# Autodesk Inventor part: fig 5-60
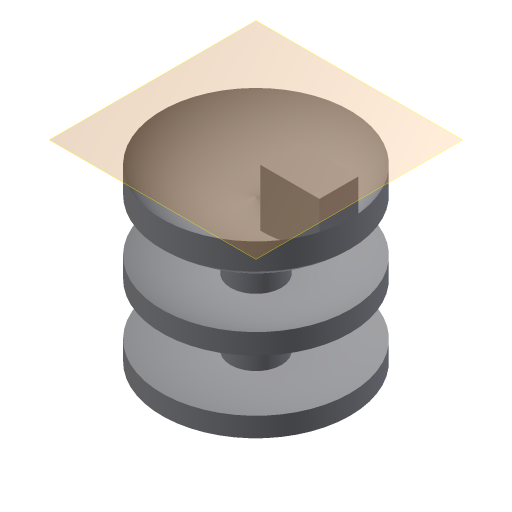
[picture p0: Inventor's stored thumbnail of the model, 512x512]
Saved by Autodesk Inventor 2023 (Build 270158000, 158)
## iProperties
Created: 2004-05
Part Number: fig 5-60
Document SubType Name: Modeling
Designer: CADCIM Technologies
Manufacturer: Standard
Standards Organization: Custom
Density: 1 g/cm^3
Material: Generic
Appearance: Default
Author: CADCIM Technologies
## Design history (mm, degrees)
sketch "Sketch1"
  geometry: L1 (0.098, 22.743)-(0.098, 0.516); L2 (-3.621, 19.305)-(-3.621, 13.061); L3 (-3.621, 10.379)-(-3.621, 3.25); L4 (-3.664, 0.516)-(0.098, 0.516); L5 (-13.694, 4.7)-(-13.694, 1.836); L6 (-13.694, 26.851)-(-13.694, 23.014); L7 (-13.694, 15.335)-(-13.694, 12.343); A1 r 10.546 centre (-4.597, 32.185) between (-13.694, 26.851) and (0.098, 22.743); A2 r 21.828 centre (-4.597, 32.185) between (-13.694, 12.343) and (-3.621, 10.379); A3 r 12.918 centre (-4.597, 32.185) between (-13.694, 23.014) and (-3.621, 19.305); A4 r 19.149 centre (-4.597, 32.185) between (-13.694, 15.335) and (-3.621, 13.061); A5 r 28.952 centre (-4.597, 32.185) between (-13.694, 4.7) and (-3.621, 3.25); A6 r 31.683 centre (-4.597, 32.185) between (-13.694, 1.836) and (-3.664, 0.516)
  constraints: 14 end point, 12 point on circle, 6 centre point, 4 perpendicular, 2 parallel, 1 vertical
revolve "Revolution1" sketch "Sketch1" stored, may be unused: angle "d0" = 90 deg
workplane "Work Plane1"
sketch "Sketch2"
  geometry: L1 (3.408, -2.846)-(12.06, -2.846); L2 (12.06, -2.846)-(12.06, 2.873); L3 (12.06, 2.873)-(3.408, 2.873); L4 (3.408, 2.873)-(3.408, -2.846)
  constraints: 8 end point, 2 parallel, 1 horizontal, 1 perpendicular
extrude "Extrusion3" join sketch "Sketch2" stored distance "d8" = 10; taper "d9" = 0 deg
body "Solid1"
